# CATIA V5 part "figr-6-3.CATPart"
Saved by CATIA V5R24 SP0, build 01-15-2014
Part number: Part1
Bounding box of the stored display mesh (mm): x -62.5 to 62.5, y -75 to 75, z 0 to 10
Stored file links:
  D:\KAVITA\CATIA V5-6R2014 Project_ Kavita\CATIA V5-6R2014_partfiles\Partfiles\c06_catia_v5-6r2014_prt\figr-6-3.CATPart
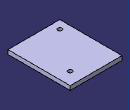
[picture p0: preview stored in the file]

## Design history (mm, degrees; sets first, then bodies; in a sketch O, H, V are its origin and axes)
Body1 (main body)
  Sketch1 on xy-plane, origin (0, 0, 0), H (1, 0, 0), V (0, 1, 0)
    line L1 (-62.5, 75) -> (62.5, 75)
    line L2 (62.5, 75) -> (62.5, -75)
    line L3 (62.5, -75) -> (-62.5, -75)
    line L4 (-62.5, -75) -> (-62.5, 75)
    axis line L5 (62.5, -75) -> (-62.5, 75)
    length L2 = 150
    length L3 = 125
    horizontal: L1 H, L3 H
    vertical: L2 V, L4 V
    midpoint: O L5
  Pad1: profile Sketch1, direction (0, 0, 1), length 10
  Sketch2 on face of Pad1, origin (-17.8347, -51.2044, 10), H (1, 0, 0), V (0, 1, 0)
    point P1 (-24.6653, -3.7956)
    reference projected line E1 (-44.6653, -23.7956) -> (80.3347, -23.7956) from edge [face of Pad1 | face of Pad1]
    reference projected line E2 (-44.6653, 126.2044) -> (-44.6653, -23.7956) from edge [face of Pad1 | face of Pad1]
    distance P1 E1 = 20
    distance P1 E2 = 20
  Hole1: placed by Sketch2, at (-42.5, -55, 10) direction (0, 0, -1), diameter 10, through (limit type 3)
  Sketch3 on face of Pad1, origin (35.5503, 42.9865, 10), H (1, 0, 0), V (0, 1, 0)
    point P1 (-3.0503, 2.0135)
    reference projected line E1 (26.9497, -117.9865) -> (26.9497, 32.0135) from edge [face of Pad1 | face of Pad1]
    reference projected line E2 (26.9497, 32.0135) -> (-98.0503, 32.0135) from edge [face of Pad1 | face of Pad1]
    distance P1 E1 = 30
    distance P1 E2 = 30
  Hole2: placed by Sketch3, at (32.5, 45, 10) direction (0, 0, -1), diameter 10, through (limit type 3)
